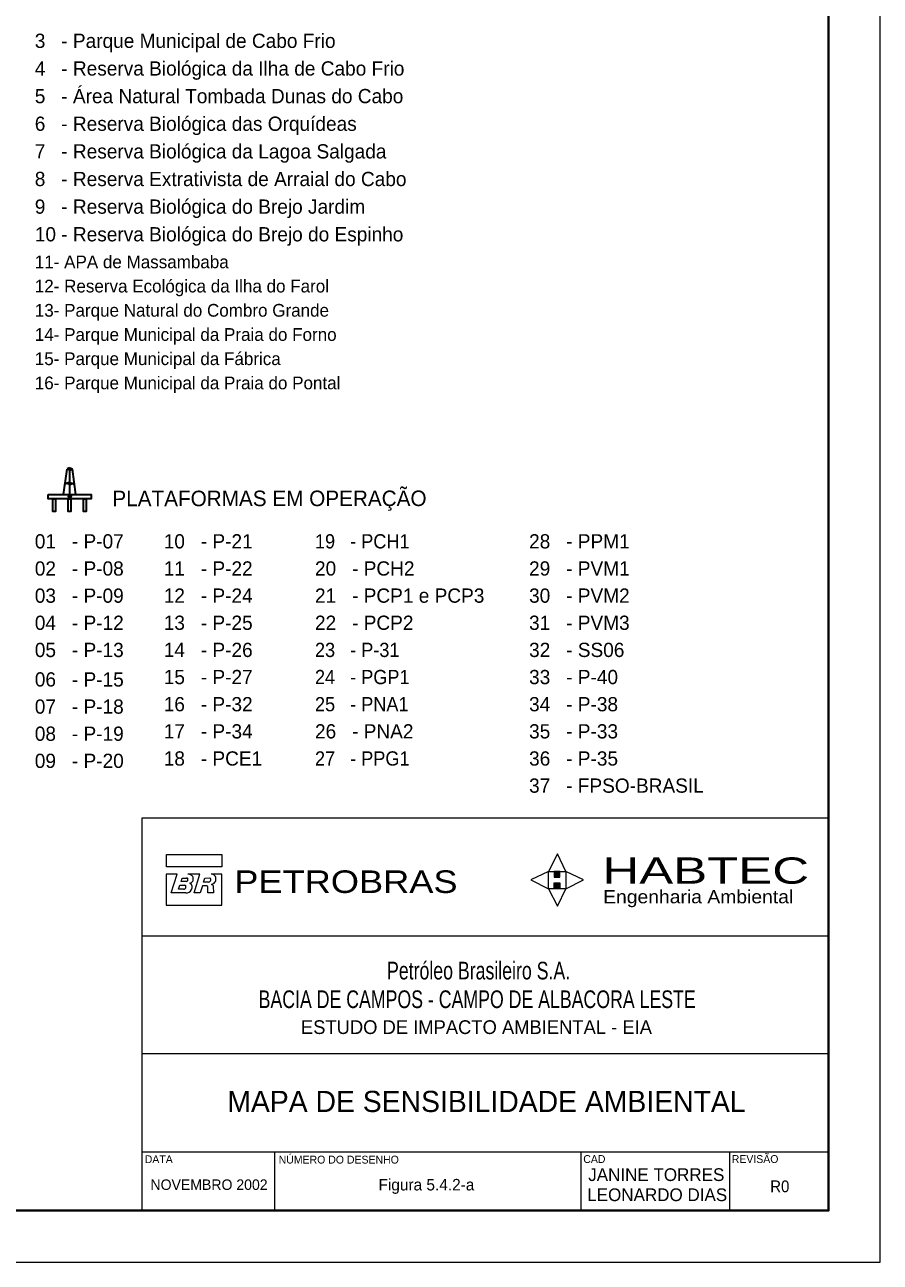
# Model space of a CAD drawing. Extents: x -6.3 to 58.7, y 19.8 to 60.6.
# Drawn here: x 44.83 to 58.68, y 19.82 to 39.84 of the extents above; entities that cross this region are included whole.
import ezdxf
from ezdxf.enums import TextEntityAlignment as Align

# ---------------------------------------------------------------- set-up
doc = ezdxf.new("R2010")
doc.units = 0
doc.header["$LTSCALE"] = 0.092
doc.header["$PDMODE"] = 32
doc.header["$PDSIZE"] = 0.046
doc.layers.add('57', color=7, linetype='Continuous')
for name, color, linetype, lineweight in [('58', 7, 'Continuous', 13), ('60', 7, 'Continuous', 40), ('63', 7, 'Continuous', 13)]:
    doc.layers.add(name, color=color, linetype=linetype, lineweight=lineweight)

msp = doc.modelspace()

# ---------------------------------------------------------------- hatches: boundary and pattern name
at = {"layer": '58'}
for points in [[(53.39607, 26.04717), (53.49131, 26.04717), (53.49131, 26.13871), (53.39607, 26.13871)], [(53.39607, 25.95604), (53.49131, 25.95604), (53.49131, 25.86079), (53.39607, 25.86079)]]:
    msp.add_hatch(color=256, dxfattribs=at).paths.add_polyline_path(points)

# ---------------------------------------------------------------- linework, layer by layer
at = {"layer": '58', "lineweight": 35}
for p, q in [((45.45881, 32.24364), (45.51587, 32.65202)), ((45.55773, 32.63681), (45.51587, 32.65202)), ((45.55773, 32.67295), (45.51677, 32.65694)), ((45.55773, 32.67295), (45.60066, 32.65613)), ((45.55773, 32.63681), (45.60138, 32.65282)), ((45.65683, 32.24364), (45.60138, 32.65282)), ((45.55773, 32.24364), (45.55773, 32.63681)), ((45.55773, 32.43978), (45.48242, 32.41053)), ((45.55773, 32.40213), (45.48475, 32.42976)), ((45.55773, 32.43817), (45.63411, 32.40964)), ((45.55773, 32.40463), (45.63161, 32.43227))]:
    msp.add_line(p, q, dxfattribs=at)
at = {"layer": '58'}
for p, q in [((47.37491, 26.03564), (47.45218, 26.03564)), ((47.74259, 26.03564), (47.82315, 26.03632)), ((47.33896, 25.92049), (47.42034, 25.92159)), ((47.77457, 25.90951), (47.77539, 25.91047)), ((46.72369, 25.09977), (57.84015, 25.09977)), ((46.72369, 23.19415), (48.55178, 23.19415)), ((48.55178, 23.19415), (55.91957, 23.19415)), ((55.91957, 23.19415), (57.84015, 23.19415)), ((57.84015, 21.92382), (57.84015, 20.65308)), ((46.72369, 21.60624), (48.55178, 21.60624)), ((48.55178, 21.60624), (55.91957, 21.60624)), ((48.87512, 20.65308), (48.87512, 21.60624)), ((53.83662, 20.65308), (53.83662, 21.60624)), ((55.91957, 21.60624), (57.84015, 21.60624)), ((56.24305, 20.65308), (56.24305, 21.60624))]:
    msp.add_line(p, q, dxfattribs=at)
at = {"layer": '58', "lineweight": 35}
for points in [[(45.20642, 32.24364), (45.90582, 32.24364), (45.90582, 32.17066), (45.20642, 32.17066)], [(45.2853, 32.17066), (45.32805, 32.17066), (45.32805, 31.96692), (45.2853, 31.96692)], [(45.5343, 32.17066), (45.57705, 32.17066), (45.57705, 31.96692), (45.5343, 31.96692)], [(45.78079, 32.17066), (45.82372, 32.17066), (45.82372, 31.96692), (45.78079, 31.96692)]]:
    msp.add_lwpolyline(points, close=True, dxfattribs=at)
at = {"layer": '58'}
for points in [[(55.91957, 20.65308), (57.84015, 20.65308), (57.84015, 27.00568), (46.72369, 27.00568), (46.72369, 20.65308), (48.55178, 20.65308)], [(47.12307, 26.41649), (48.01721, 26.41649), (48.01721, 26.21886), (47.12307, 26.21886)], [(53.58697, 26.13871), (53.45165, 26.42898), (53.30851, 26.13871)], [(53.30851, 26.13871), (53.02263, 26.0038), (53.30851, 25.86079)], [(53.39607, 26.04717), (53.49131, 26.04717), (53.49131, 26.13871), (53.39607, 26.13871)], [(53.58697, 25.86079), (53.87285, 26.0038), (53.58697, 26.13871)], [(53.30851, 25.86079), (53.45165, 25.57862), (53.58697, 25.86079)], [(53.39607, 25.95604), (53.49131, 25.95604), (53.49131, 25.86079), (53.39607, 25.86079)]]:
    msp.add_lwpolyline(points, close=True, dxfattribs=at)
for points in [[(47.29572, 26.09987), (47.11991, 26.09987), (47.11909, 25.59824), (48.0179, 25.59824), (48.01721, 26.09891), (47.8458, 26.09891)], [(47.43599, 25.79382), (47.19883, 25.79327), (47.29572, 26.09987)], [(47.44916, 25.98102), (47.35831, 25.98102), (47.37491, 26.03564)], [(47.77539, 25.91047), (47.7043, 25.91116), (47.66752, 25.79327), (47.56898, 25.79464), (47.66505, 26.09987), (47.46879, 26.09987)], [(47.80435, 25.96674), (47.72228, 25.96743), (47.74259, 26.03564)], [(47.39687, 25.85269), (47.317, 25.85324), (47.33896, 25.92049)], [(47.88093, 25.90334), (47.88258, 25.79382), (47.79104, 25.79382), (47.79186, 25.88851)]]:
    msp.add_lwpolyline(points, dxfattribs=at)
for centre, radius, start, end in [((47.45213, 26.01632), 0.01956, 33.25984, 90.09984), ((47.45215, 25.96361), 0.13752, 56.10871, 83.28784), ((47.50041, 26.02778), 0.0575, 10.8397, 60.37107), ((47.44249, 26.02881), 0.11481, 337.03887, 4.89174), ((47.81678, 26.01188), 0.02537, 9.43899, 74.45349), ((47.83572, 26.00298), 0.09767, 43.75156, 84.44063), ((47.84563, 26.02358), 0.07669, 352.58157, 37.74009), ((47.38783, 25.91295), 0.06052, 278.29672, 308.83753), ((47.41713, 25.89949), 0.02211, 21.7795, 80.41438), ((47.40856, 25.89053), 0.03012, 304.84956, 350.67141), ((47.43419, 25.90566), 0.11142, 270.90956, 328.37896), ((47.37007, 25.89474), 0.06882, 352.40431, 10.84359), ((47.44375, 26.00718), 0.02684, 280.80155, 331.0851), ((47.43747, 26.01108), 0.03423, 330.45216, 6.63993), ((47.43739, 26.01295), 0.03414, 3.50787, 24.38053), ((47.49642, 26.00971), 0.05781, 274.56826, 333.61026), ((47.47852, 25.89645), 0.06002, 7.51889, 67.97955), ((47.42557, 25.89269), 0.11305, 336.29285, 5.89541), ((47.76479, 25.88462), 0.02749, 10.87031, 68.41561), ((47.80312, 26.00344), 0.03541, 271.6889, 333.12069), ((47.79564, 26.01232), 0.04633, 327.50113, 4.59918), ((47.82628, 26.02759), 0.10032, 285.23249, 312.72557), ((47.84523, 25.88986), 0.0416, 46.7371, 79.73619), ((47.84933, 25.89685), 0.03375, 11.19479, 43.67445), ((47.84313, 26.01344), 0.07854, 310.69969, 0.17337)]:
    msp.add_arc(centre, radius, start, end, dxfattribs=at)
for p in [(45.55523, 32.21091), (45.56363, 32.21341)]:
    msp.add_point(p, dxfattribs=at)
at = {"layer": '60'}
msp.add_lwpolyline([(-3.73781, 29.96257), (-3.73781, 20.65308), (57.84015, 20.65308), (57.84016, 59.74412), (-3.73781, 59.74412), (-3.73781, 40.1986), (-3.73781, 40.1986)], dxfattribs=at)
at = {"layer": '63'}
msp.add_lwpolyline([(-6.28685, 19.8174), (58.67584, 19.8174), (58.67584, 60.5798), (-6.28685, 60.5798)], close=True, dxfattribs=at)

# ---------------------------------------------------------------- texts
at = {"layer": '57'}
for s, p in [('JANINE TORRES', (55.05096, 21.13192)), ('LEONARDO DIAS', (55.06579, 20.80679))]:
    msp.add_text(s, height=0.2059, dxfattribs=at).set_placement(p, align=Align.CENTER)
at = {"layer": '58'}
for s, height, p in [('3   - Parque Municipal de Cabo Frio', 0.2306, (44.99192, 39.46892)), ('4   - Reserva Biológica da Ilha de Cabo Frio', 0.2306, (44.99192, 39.02169)), ('5   - Área Natural Tombada Dunas do Cabo', 0.2306, (44.99192, 38.57447)), ('6   - Reserva Biológica das Orquídeas', 0.2306, (44.99192, 38.12725)), ('7   - Reserva Biológica da Lagoa Salgada', 0.2306, (44.99192, 37.68003)), ('8   - Reserva Extrativista de Arraial do Cabo', 0.2306, (44.99192, 37.23281)), ('9   - Reserva Biológica do Brejo Jardim', 0.2306, (44.99192, 36.78559)), ('10 - Reserva Biológica do Brejo do Espinho', 0.2306, (44.99192, 36.33837)), ('11- APA de Massambaba', 0.206, (44.99192, 35.90343)), ('12- Reserva Ecológica da Ilha do Farol', 0.206, (44.99192, 35.51168)), ('13- Parque Natural do Combro Grande', 0.206, (44.99192, 35.11993)), ('14- Parque Municipal da Praia do Forno', 0.206, (44.99192, 34.72817)), ('15- Parque Municipal da Fábrica', 0.206, (44.99192, 34.33651)), ('16- Parque Municipal da Praia do Pontal', 0.206, (44.99192, 33.94476)), ('01   - P-07', 0.2306, (44.99192, 31.36911)), ('10   - P-21', 0.2306, (47.07856, 31.36911)), ('28   - PPM1', 0.2306, (52.99201, 31.36911)), ('02   - P-08', 0.2306, (44.99192, 30.92926)), ('11   - P-22', 0.2306, (47.07856, 30.92982)), ('20   - PCH2', 0.2306, (49.52663, 30.92982)), ('29   - PVM1', 0.2306, (52.99201, 30.92982)), ('03   - P-09', 0.2306, (44.99192, 30.48997)), ('12   - P-24', 0.2306, (47.07856, 30.49054)), ('21   - PCP1 e PCP3', 0.2306, (49.52663, 30.49054)), ('30   - PVM2', 0.2306, (52.99201, 30.49054)), ('04   - P-12', 0.2306, (44.99192, 30.05069)), ('13   - P-25', 0.2306, (47.07856, 30.05125)), ('22   - PCP2', 0.2306, (49.52663, 30.05125)), ('31   - PVM3', 0.2306, (52.99201, 30.05125)), ('05   - P-13', 0.2306, (44.99192, 29.6114)), ('14   - P-26', 0.2306, (47.07856, 29.61197)), ('32   - SS06', 0.2306, (52.99201, 29.61197)), ('06   - P-15', 0.2306, (44.99192, 29.13429)), ('15   - P-27', 0.2306, (47.07856, 29.17268)), ('33   - P-40', 0.2306, (52.99201, 29.17268)), ('07   - P-18', 0.2306, (44.99192, 28.69501)), ('16   - P-32', 0.2306, (47.07856, 28.7334)), ('34   - P-38', 0.2306, (52.99201, 28.7334)), ('08   - P-19', 0.2306, (44.99192, 28.25572)), ('17   - P-34', 0.2306, (47.07856, 28.29411)), ('26   - PNA2', 0.2306, (49.52663, 28.29411)), ('35   - P-33', 0.2306, (52.99201, 28.29411)), ('09   - P-20', 0.2306, (44.99192, 27.81644)), ('18   - PCE1', 0.2306, (47.07856, 27.85483)), ('36   - P-35', 0.2306, (52.99201, 27.85483)), ('37   - FPSO-BRASIL', 0.2306, (52.99201, 27.41554))]:
    msp.add_text(s, height=height, dxfattribs=at).set_placement(p)
msp.add_text('PLATAFORMAS EM OPERAÇÃO', height=0.2507, rotation=0.028, dxfattribs=at).set_placement((48.79017, 32.054), align=Align.CENTER)
for s, height, width, p in [('19   - PCH1', 0.2306, 0.95, (49.52663, 31.36911)), ('23   - P-31', 0.2306, 0.95, (49.52663, 29.61197)), ('24   - PGP1', 0.2306, 0.95, (49.52663, 29.17268)), ('25   - PNA1', 0.2306, 0.95, (49.52663, 28.7334)), ('27   - PPG1', 0.2306, 0.95, (49.52663, 27.85483)), ('HABTEC', 0.4251, 1.45, (54.18014, 25.94341)), ('PETROBRAS', 0.3651, 1.2, (48.22061, 25.79382)), ('Engenharia Ambiental', 0.2126, 1.1, (54.19043, 25.62638))]:
    msp.add_text(s, height=height, dxfattribs=dict(at, width=width)).set_placement(p)
for s, height, width, p in [('Petróleo Brasileiro S.A.', 0.2859, 0.75, (52.17483, 24.3942)), ('BACIA DE CAMPOS - CAMPO DE ALBACORA LESTE', 0.2859, 0.75, (52.15184, 23.93087)), ('R0', 0.1906, 0.95, (57.05013, 20.95049))]:
    msp.add_text(s, height=height, dxfattribs=dict(at, width=width)).set_placement(p, align=Align.CENTER)
for s, height, p in [('ESTUDO DE IMPACTO AMBIENTAL - EIA', 0.2223, (52.14007, 23.51104)), ('MAPA DE SENSIBILIDADE AMBIENTAL', 0.3431, (52.30198, 22.24831)), ('DATA', 0.1271, (46.9981, 21.42096)), ('NÚMERO DO DESENHO', 0.1271, (49.91157, 21.41437)), ('CAD', 0.1271, (54.04875, 21.42398)), ('REVISÃO', 0.127, (56.65022, 21.42398)), ('NOVEMBRO 2002', 0.17, (47.81204, 20.98777)), ('Figura 5.4.2-a', 0.1864, (51.33043, 20.97958))]:
    msp.add_text(s, height=height, dxfattribs=at).set_placement(p, align=Align.CENTER)

doc.saveas('drawing.dxf')
